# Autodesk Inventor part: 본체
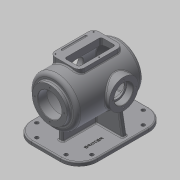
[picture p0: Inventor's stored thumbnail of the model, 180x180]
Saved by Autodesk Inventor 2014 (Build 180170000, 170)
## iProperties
Created: 2016-02
Part Number: 본체
Material: 일반
Document SubType Name: Modeling
Designer: mduedu
Density: 2.71 g/cm^3
Appearance: Default
Author: mduedu
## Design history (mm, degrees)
sketch "스케치2"
  geometry: L1 (0, 100)-(0, -100); L2 (65, -75.993)-(65, 100); L3 (65, 100)-(0, 100); A1 r 100 centre (0, 0) between (0, -100) and (65, -75.993); 2 further points
  constraints: 6 end point, 2 midpoint, 2 point on circle, 1 centre point, 1 coincident, 1 horizontal, 1 parallel, 1 vertical
  dimensions: "d3" = 200 distance of L1.start L1.end; "d5" = 130 diameter of L2 L1; "d6" = 100 radius of A1
revolve "회전1" sketch "스케치2" stored, may be unused: angle "d7" = 90 deg
sketch "스케치3"
  geometry: C1 r 47.5 at (0, 0); 1 further point
  constraints: 1 centre point, 1 coincident
  dimensions: "d8" = 95 diameter of C1
extrude "돌출2" join sketch "스케치3" distance "d10" = 10; taper "d11" = 0 deg
sketch "스케치5"
  geometry: L1 (47.5, 110)-(47.5, 100) reference; L2 (47.5, 100)-(65, 100) reference; L3 (65, 100)-(65, -75.993) reference; L4 (-65, -75.993)-(-65, 100) reference; L5 (-65, 100)-(-47.5, 100) reference; L6 (-47.5, 100)-(-47.5, 110) reference; L7 (-47.5, 110)-(47.5, 110) reference; L8 (55, 85)-(55, -71.239); L9 (0, 85)-(55, 85); L10 (0, 85)-(0, -90); A1 r 100 centre (0, 0) between (0, -100) and (65, -75.993) reference; A2 r 100 centre (0, 0) between (-65, -75.993) and (0, -100) reference; A3 r 90 centre (0, 0) between (0, -90) and (55, -71.239); 1 further point
  constraints: 6 end point, 2 point on circle, 1 centre point, 1 parallel, 1 perpendicular, 1 point on line, 1 vertical
  dimensions: "d13" = 10 distance between parallel lines of L3 L8; "d14" = 10 radial gap between concentric circles of A3 A1; "d15" = 15 distance between parallel lines of L9 L2
revolve "회전2" sketch "스케치5" stored, may be unused: angle "d16" = 90 deg
hole "구멍1" diameter "d19" = 65; stored, may be unused: countersink angle "d23" = 90 deg, drill point angle "d25" = 118 deg; dims "d17" = 10, "d18" = 10, "d20" = 6, "d21" = 4, "d22" = 2, "d24" = 8
node "작업 평면1"
sketch "스케치6"
  geometry: L1 (47.5, 110)-(-47.5, 110) reference; C1 r 40 at (0, -17); 1 further point
  constraints: 1 centre point, 1 vertical alignment
  dimensions: "d27" = 80 diameter of C1; "d29" = 127 distance from line of C1.centre L1
extrude "돌출3" join sketch "스케치6" stored distance "d30" = 10; taper "d31" = 0 deg
hole "구멍2" diameter "d34" = 42; stored, may be unused: countersink angle "d38" = 90 deg, drill point angle "d40" = 118 deg; dims "d32" = 10, "d33" = 10, "d35" = 6, "d36" = 52, "d37" = 18, "d39" = 8
sketch "스케치7" dims "d41" = 65
  geometry: C1 r 40 at (0, 0) reference; 3 further points
  constraints: 2 vertical alignment, 1 coincident, 2 other
hole "구멍3" sketch "스케치7" at (0, 32.5) diameter "d43" = 3.242; stored, may be unused: countersink angle "d47" = 90 deg, drill point angle "d49" = 118 deg; dims "d44" = 11, "d45" = 13, "d46" = 18, "d48" = 13
sketch "스케치8" dims "d53" = 80
  geometry: 3 further points
  constraints: 2 vertical alignment, 1 coincident, 2 other
hole "구멍4" sketch "스케치8" at (0, 40) diameter "d56" = 3.242; stored, may be unused: countersink angle "d60" = 90 deg, drill point angle "d62" = 118 deg; dims "d57" = 11, "d58" = 13, "d59" = 18, "d61" = 13
fillet "모깎기1" dims "d66" = 10
fillet "모깎기2" dims "d67" = 3
fillet "모깎기3" dims "d68" = 0.3
chamfer "모따기1" distance "d69" = 1; stored, may be unused: second distance "d70" = 2, angle "d71" = 45 deg
node "작업 평면5"
sketch "스케치23"
  geometry: L1 (6, 80)-(-6, 80); L2 (-6, 80)-(-6, -60); L3 (-6, -60)-(6, -60); L4 (6, -60)-(6, 80); L5 (-55, 100)-(55, 100) reference; 2 further points
  constraints: 8 end point, 2 parallel, 1 horizontal, 1 midpoint, 1 perpendicular, 1 vertical alignment
  dimensions: "d177" = 12 distance of L1.start L1.end; "d179" = 140 distance of L3.end L1.start; "d180" = 20 distance between parallel lines of L1 L5
extrude "돌출14" join sketch "스케치23" stored distance "d181" = 10; taper "d182" = 0 deg
node "작업 평면6"
sketch "스케치15"
  geometry: L1 (-30, 60)-(50, 60); L2 (50, 60)-(50, -60); L3 (50, -60)-(-30, -60); L4 (-30, -60)-(-30, 60); 3 further points
  constraints: 8 end point, 2 parallel, 1 horizontal, 1 horizontal alignment, 1 midpoint, 1 perpendicular, 1 vertical alignment
  dimensions: "d110" = 80 distance of L2.end L3.end; "d112" = 60 distance from line of L3 point (10, 0); "d113" = 120 distance of L1.end L2.end; "d149" = 30 distance from line of L4 point (0, 0)
extrude "돌출8" join sketch "스케치15" stored distance "d114" = 10; taper "d115" = 0 deg
fillet "모깎기7" dims "d116" = 15
sketch "스케치16"
  geometry: L1 (-30, -45)-(-30, 45) reference; L2 (-15, 60)-(35, 60) reference; L3 (35, -60)-(-15, -60) reference; L4 (-20, -45)-(-20, 45); L5 (-15, 50)-(15, 50); L6 (20, 45)-(20, -45); L7 (15, -50)-(-15, -50); L8 (50, 45)-(50, -45) reference; A1 r 15 centre (-15, -45) between (-30, -45) and (-15, -60) reference; A2 r 15 centre (-15, 45) between (-15, 60) and (-30, 45) reference; A3 r 5 centre (-15, -45) between (-20, -45) and (-15, -50); A4 r 5 centre (-15, 45) between (-15, 50) and (-20, 45); A5 r 5 centre (15, 45) between (20, 45) and (15, 50); A6 r 5 centre (15, -45) between (15, -50) and (20, -45); A7 r 15 centre (35, 45) between (50, 45) and (35, 60) reference; A8 r 15 centre (35, -45) between (35, -60) and (50, -45) reference
  constraints: 8 end point, 8 point on circle, 4 centre point, 2 equal radius, 3 other
  dimensions: "d137" = 10 distance between parallel lines of L4 L1; "d150" = 40 distance between parallel lines of L6 L4; "d151" = 100 distance between parallel lines of L7 L5
extrude "돌출9" cut sketch "스케치16" stored distance "d118" = 10; taper "d119" = 0 deg
fillet "모깎기8" dims "d120" = 3
sketch "스케치17"
  geometry: L1 (-30, -45)-(-30, 45) reference; L2 (-20, 45)-(-20, -45) reference; L3 (-15, -50)-(15, -50) reference; L4 (20, -45)-(20, 45) reference; L5 (15, 50)-(-15, 50) reference; L6 (-15, 60)-(35, 60) reference; L7 (35, -60)-(-15, -60) reference; L8 (15, 55)-(-15, 55); L9 (-25, 45)-(-25, -45); L10 (-15, -55)-(15, -55); L11 (25, -45)-(25, 45); L12 (50, 45)-(50, -45) reference; L13 (35, 55)-(-15, 55); L14 (-25, 45)-(-25, -45); L15 (-15, -55)-(35, -55); L16 (45, -45)-(45, 45); A1 r 5 centre (-15, 45) between (-15, 50) and (-20, 45) reference; A2 r 5 centre (-15, -45) between (-20, -45) and (-15, -50) reference; A3 r 5 centre (15, -45) between (15, -50) and (20, -45) reference; A4 r 5 centre (15, 45) between (20, 45) and (15, 50) reference; A5 r 15 centre (-15, 45) between (-15, 60) and (-30, 45) reference; A6 r 15 centre (-15, -45) between (-30, -45) and (-15, -60) reference; A7 r 10 centre (-15, 45) between (-15, 55) and (-25, 45); A8 r 10 centre (-15, -45) between (-25, -45) and (-15, -55); A9 r 10 centre (15, -45) between (15, -55) and (25, -45); A10 r 10 centre (15, 45) between (25, 45) and (15, 55); A11 r 15 centre (35, 45) between (50, 45) and (35, 60) reference; A12 r 15 centre (35, -45) between (35, -60) and (50, -45) reference; A13 r 10 centre (-15, 45) between (-15, 55) and (-25, 45); A14 r 10 centre (-15, -45) between (-25, -45) and (-15, -55); A15 r 10 centre (35, -45) between (35, -55) and (45, -45); A16 r 10 centre (35, 45) between (45, 45) and (35, 55); 6 further points
  constraints: 18 point on circle, 16 end point, 8 centre point, 4 midpoint, 4 tangent, 11 other
  dimensions: "d138" = 5 distance between parallel lines of L8 L6; "d157" = 5 distance between parallel lines of L12 L16
hole "구멍5" sketch "스케치17" at (-25, 0), (42.071, 52.071), (42.071, -52.071) diameter "d122" = 3.242; stored, may be unused: countersink angle "d126" = 90 deg, drill point angle "d128" = 118 deg; dims "d123" = 9, "d124" = 13, "d125" = 18, "d127" = 11
sketch "스케치19"
  geometry: L1 (-50, 70)-(-35, 70) reference; L2 (-50, 42.603)-(-50, 70) reference; C1 r 2.5 at (-43, 70); 1 further point
  constraints: 1 centre point, 1 point on line
  dimensions: "d152" = 5 diameter of C1; "d153" = 7 distance from line of C1.centre L2
extrude "돌출11" cut sketch "스케치19" stored distance "d154" = 70; taper "d155" = 0 deg
fillet "모깎기11" dims "d156" = 2.5
sketch "스케치20"
  geometry: L1 (-90, 120)-(90, 120); L2 (90, 120)-(90, -120); L3 (90, -120)-(-90, -120); L4 (-90, -120)-(-90, 120); 3 further points
  constraints: 8 end point, 2 parallel, 2 vertical alignment, 1 coincident, 1 horizontal, 1 midpoint, 1 perpendicular
  dimensions: "d162" = 180 distance of L1.start L1.end; "d164" = 240 distance of L1.end L2.end; "d165" = 120 distance from line of L1 point (0, 0)
extrude "돌출12" join sketch "스케치20" distance "d166" = 10; taper "d167" = 0 deg
fillet "모깎기12" dims "d168" = 50
node "작업 평면8"
  node "작업축1"
sketch "스케치24"
  geometry: L1 (128, 34.121)-(127.026, 32.5) reference; L2 (127.026, 32.5)-(128, 30.879) reference; L3 (128, 30.879)-(141, 30.879) reference; L4 (141, 30.879)-(141, 27) reference; L5 (141, 27)-(140, 26) reference; L6 (140, 26)-(123.3, 26) reference; L7 (123, 25.7)-(123, 21) reference; L8 (123, 21)-(116.833, 21) reference; L9 (86, 51.235)-(86, 70) reference; L10 (86, 70)-(106.5, 70) reference; L11 (111.5, 70)-(116, 70) reference; L12 (116, 70)-(116, 42.603) reference; L13 (118.678, 40)-(141, 40) reference; L14 (141, 40)-(141, 34.121) reference; L15 (141, 34.121)-(128, 34.121) reference; L16 (4, -34.121)-(4.974, -32.5) reference; L17 (4.974, -32.5)-(4, -30.879) reference; L18 (4, -30.879)-(-9, -30.879) reference; L19 (-9, -30.879)-(-9, -27) reference; L20 (-9, -27)-(-8, -26) reference; L21 (-8, -26)-(8.7, -26) reference; L22 (9, -25.7)-(9, -21) reference; L23 (9, -21)-(15.167, -21) reference; L24 (116.833, -21)-(123, -21) reference; L25 (123, -21)-(123, -25.7) reference; L26 (123.3, -26)-(140, -26) reference; L27 (140, -26)-(141, -27) reference; L28 (141, -27)-(141, -30.879) reference; L29 (141, -30.879)-(128, -30.879) reference; L30 (128, -30.879)-(127.026, -32.5) reference; L31 (127.026, -32.5)-(128, -34.121) reference; L32 (128, -34.121)-(141, -34.121) reference; L33 (141, -34.121)-(141, -40) reference; L34 (141, -40)-(118.678, -40) reference; L35 (72, -64.722)-(72, -100) reference; L36 (72, -100)-(156, -100) reference; L37 (156, -100)-(156, -110) reference; L38 (156, -110)-(-24, -110) reference; L39 (-24, -110)-(-24, -100) reference; L40 (-24, -100)-(60, -100) reference; L41 (60, -100)-(60, -64.722) reference; L42 (13.322, -40)-(-9, -40) reference; L43 (-9, -40)-(-9, -34.121) reference; L44 (-9, -34.121)-(4, -34.121) reference; L45 (4.974, 32.5)-(4, 34.121) reference; L46 (4, 34.121)-(-9, 34.121) reference; L47 (-9, 34.121)-(-9, 40) reference; L48 (-9, 40)-(13.322, 40) reference; L49 (36, 59.456)-(36, 70) reference; L50 (36, 70)-(46, 70) reference; L51 (46, 70)-(46, 51.235) reference; L52 (15.167, 21)-(9, 21) reference; L53 (9, 21)-(9, 25.7) reference; L54 (8.7, 26)-(-8, 26) reference; L55 (-8, 26)-(-9, 27) reference; L56 (-9, 27)-(-9, 30.879) reference; L57 (-9, 30.879)-(4, 30.879) reference; L58 (4, 30.879)-(4.974, 32.5) reference; L59 (-1, -40)-(-11.58, -100); A1 r 0.3 centre (123.3, 25.7) between (123.3, 26) and (123, 25.7) reference; A2 r 55 centre (66, 0) between (116.833, 21) and (86, 51.235) reference; A3 r 2.5 centre (109, 70) between (106.5, 70) and (111.5, 70) reference; A4 r 3 centre (119, 42.603) between (116, 42.603) and (116.516, 40.92) reference; A5 r 0.3 centre (8.7, -25.7) between (8.7, -26) and (9, -25.7) reference; A6 r 55 centre (66, 0) between (15.167, -21) and (116.833, -21) reference; A7 r 0.3 centre (123.3, -25.7) between (123, -25.7) and (123.3, -26) reference; A8 r 65 centre (66, 0) between (72, -64.722) and (116.354, -41.103) reference; A9 r 65 centre (66, 0) between (15.646, -41.103) and (60, -64.722) reference; A10 r 65 centre (66, 0) between (34.456, 56.833) and (15.646, 41.103) reference; A11 r 3 centre (33, 59.456) between (34.456, 56.833) and (36, 59.456) reference; A12 r 55 centre (66, 0) between (46, 51.235) and (15.167, 21) reference; A13 r 0.3 centre (8.7, 25.7) between (9, 25.7) and (8.7, 26) reference; 1 further point
  constraints: 2 end point, 2 point on line, 4 other
  dimensions: "d184" = 8 distance of L59.start L42.end; "d185" = 100 deg angle of L59 L40
feature "리브2" sketch "스케치24" dims "d186" = 1, "d187" = 12, "d188" = 0, "d189" = 0, "d190" = 1, "d191" = 1
fillet "모깎기15" dims "d192" = 3
fillet "모깎기16" dims "d193" = 3
sketch "스케치25"
  geometry: L1 (90, -70)-(90, 70) reference; L2 (40, 120)-(-40, 120) reference; L3 (-90, 70)-(-90, -70) reference; L4 (-40, -120)-(40, -120) reference; L5 (-74.004, 8)-(-9, 8) reference; L6 (-80.097, 20)-(-80.097, 14) reference; L7 (-9, 26)-(-74.004, 26) reference; L8 (-9, 57)-(-9, 26) reference; L9 (3, 63)-(-3, 63) reference; L10 (9, 26)-(9, 57) reference; L11 (74.004, 26)-(9, 26) reference; L12 (80.097, 14)-(80.097, 20) reference; L13 (9, 8)-(74.004, 8) reference; L14 (9, -77)-(9, 8) reference; L15 (-3, -83)-(3, -83) reference; L16 (-9, 8)-(-9, -77) reference; L17 (-40, 105)-(40, 105); L18 (75, 70)-(75, -70); L19 (40, -105)-(-40, -105); L20 (-75, -70)-(-75, 70); C1 r 5 at (-75, 70); C2 r 5 at (-40, 105); C3 r 5 at (40, 105); C4 r 5 at (75, 70); C5 r 5 at (75, -70); C6 r 5 at (40, -105); C7 r 5 at (-40, -105); C8 r 5 at (-75, -70); A1 r 50 centre (40, 70) between (90, 70) and (40, 120) reference; A2 r 50 centre (-40, 70) between (-40, 120) and (-90, 70) reference; A3 r 50 centre (-40, -70) between (-90, -70) and (-40, -120) reference; A4 r 50 centre (40, -70) between (40, -120) and (90, -70) reference; A5 r 6 centre (-3, 57) between (-3, 63) and (-9, 57) reference; A6 r 6 centre (3, 57) between (9, 57) and (3, 63) reference; A7 r 6 centre (3, -77) between (3, -83) and (9, -77) reference; A8 r 6 centre (-3, -77) between (-9, -77) and (-3, -83) reference; A9 r 35 centre (40, 70) between (75, 70) and (40, 105); A10 r 35 centre (40, -70) between (40, -105) and (75, -70); A11 r 35 centre (-40, -70) between (-75, -70) and (-40, -105); A12 r 35 centre (-40, 70) between (-40, 105) and (-75, 70); 5 further points; 4 other entities
  constraints: 12 centre point, 8 coincident, 8 end point, 8 point on circle, 7 equal radius, 11 other
  dimensions: "d194" = 15 distance between parallel lines of L17 L2; "d195" = 10 diameter of C1
extrude "돌출15" cut sketch "스케치25" stored distance "d197" = 10; taper "d198" = 0 deg
fillet "모깎기14" dims "d170" = 3
sketch "스케치22"
  geometry: L1 (90, -70)-(90, 70) reference; 2 further points
  constraints: 1 other
  dimensions: "d174" = 40 distance from line of L1 point (50, -40); "d199" = 40 vertical distance of point (50, -40) point (0, 0)
feature "엠보싱2" sketch "스케치22" dims "d13" = 10, "d175" = 0.5, "d176" = 0
node "솔리드2"
pattern_circular "원형 패턴1" dims angle "d51" = 360 deg
mirror "대칭1"
pattern_circular "원형 패턴2" dims angle "d64" = 360 deg
mirror "대칭3"
node "투영된 루프2"
node "절단 모서리 투영1"
node "절단 모서리 투영2"
node "절단 모서리 투영3"
node "절단 모서리 투영4"
other parameters: "d26" = 75, "d183" = 0
